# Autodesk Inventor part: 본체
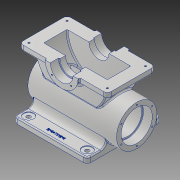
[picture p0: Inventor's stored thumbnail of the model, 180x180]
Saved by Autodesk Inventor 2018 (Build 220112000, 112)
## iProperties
Created: 2023-07
Part Number: 본체
Material: 알루미늄 6061
Document SubType Name: Modeling
Designer: 강의실04
Density: 2.7 g/cm^3
Appearance: 알루미늄 - 평지
Mass: 5728.17 g
Surface Area: 2845.94 cm^2
Volume: 2121.54 cm^3
Author: 강의실04
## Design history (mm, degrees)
sketch "스케치1"
  geometry: C1 r 55 at (0, 0); 1 further point
  constraints: 1 centre point, 1 coincident
  dimensions: "d0" = 110 diameter of C1
extrude "돌출1" new body sketch "스케치1" distance "d1" = 107; taper "d3" = 0 deg; dims "d2" = 135, "d4" = 0
node "작업 평면5"
sketch "스케치31"
  geometry: L1 (65, 120)-(-65, 120); L2 (-65, 120)-(-65, -120); L3 (-65, -120)-(65, -120); L4 (65, -120)-(65, 120); L5 (65, 120)-(-65, -120); L6 (-65, 120)-(65, -120); 1 further point
  constraints: 12 end point, 2 midpoint, 2 parallel, 1 horizontal, 1 perpendicular
  dimensions: "d120" = 130 distance of L3.end L2.end; "d121" = 240 distance of L2.end L1.end
extrude "돌출14" join sketch "스케치31" distance "d122" = 15; taper "d123" = 0 deg
sketch "스케치33"
  geometry: L1 (100, -120)-(100, 120) reference; L2 (100, 100)-(100, -100); A1 r 100 centre (100, 0) between (100, 100) and (100, -100); 1 further point
  constraints: 2 end point, 2 point on circle, 2 point on line, 1 centre point, 1 midpoint
  dimensions: "d124" = 200 diameter of A1
extrude "돌출15" join sketch "스케치33" stored distance "d125" = 90; taper "d126" = 0 deg
sketch "스케치45"
  geometry: L1 (-70, 100)-(70, 100); L2 (65, 100)-(-65, 100) reference; L3 (-70, 100)-(-70, 85); L4 (-70, 85)-(70, 85); L5 (70, 85)-(70, 100); 2 further points
  constraints: 8 end point, 2 midpoint, 1 horizontal, 1 perpendicular, 1 vertical, 1 vertical alignment
  dimensions: "d153" = 140 distance of L1.start L1.end; "d154" = 15 distance of L1.start L3.end; "d155" = 140 distance of L3.end L4.end
revolve "회전2" sketch "스케치45" stored, may be unused: angle "d156" = 90 deg
sketch "스케치46"
  geometry: L1 (-120, 0)-(-15, 0) reference; L2 (-45, 0)-(45, 0); A1 r 45 centre (0, 0) between (-45, 0) and (45, 0); 2 further points
  constraints: 2 end point, 2 point on circle, 1 centre point, 1 coincident, 1 collinear, 1 horizontal alignment, 1 point on line
  dimensions: "d157" = 90 diameter of A1
extrude "돌출21" join sketch "스케치46" stored distance "d158" = 23; taper "d159" = 0 deg
sketch "스케치49"
  geometry: C1 r 31 at (0, 0); A1 r 45 centre (0, 0) between (-45, 0) and (45, 0) reference; 1 further point
  constraints: 1 centre point, 1 coincident
  dimensions: "d165" = 62 diameter of C1
extrude "돌출22" cut sketch "스케치49" distance "d166" = 23; taper "d167" = 0 deg
sketch "스케치50"
  geometry: C1 r 31 at (0, 0); A1 r 45 centre (0, 0) between (-45, 0) and (45, 0) reference; 1 further point
  constraints: 1 centre point, 1 coincident
  dimensions: "d168" = 62 diameter of C1
extrude "돌출23" cut sketch "스케치50" distance "d169" = 23; taper "d170" = 0 deg
sketch "스케치51"
  geometry: C1 r 27.5 at (0, 0); A1 r 15 centre (0, 0) between (15, 0) and (-15, 0) reference; 1 further point
  constraints: 1 centre point, 1 coincident
  dimensions: "d171" = 55 diameter of C1
extrude "돌출24" cut sketch "스케치51" stored distance "d172" = 23; taper "d173" = 0 deg
fillet "모깎기3" dims "d174" = 10
sketch "스케치52"
  geometry: 3 further points
  constraints: 1 horizontal alignment
  dimensions: "d175" = 52 horizontal distance of point (0, 0) point (52, 107); "d176" = 104 distance of point (-52, 107) point (52, 107); "d177" = 107 vertical distance of point (0, 0) point (52, 107)
hole "구멍2" sketch "스케치52" at (52, 107), (-52, 107) diameter "d178" = 4.917; stored, may be unused: countersink angle "d182" = 90 deg, drill point angle "d184" = 118 deg; dims "d179" = 12, "d180" = 4, "d181" = 2, "d183" = 17.1
node "작업 평면6"
sketch "스케치53"
  geometry: L1 (-100, -100)-(100, -100); L2 (100, -100)-(100, 100); L3 (100, 100)-(-100, 100); L4 (-100, 100)-(-100, -100); L5 (55, 107)-(-55, 107) reference; 1 further point
  constraints: 8 end point, 2 parallel, 1 horizontal, 1 perpendicular
  dimensions: "d189" = 200 distance of L3.end L2.end; "d190" = 200 distance of L2.end L1.end; "d192" = 100 horizontal distance of L3.end point (0, 0); "d199" = 7 distance between parallel lines of L3 L5
extrude "돌출25" join sketch "스케치53" distance "d193" = 15; taper "d194" = 0 deg
fillet "모깎기5" dims "d200" = 10
sketch "스케치55"
  geometry: 3 further points
  constraints: 1 vertical alignment
  dimensions: "d201" = 80 horizontal distance of point (80, -80) point (0, 0); "d202" = 160 distance of point (80, 80) point (80, -80); "d203" = 80 horizontal distance of point (80, -80) point (0, 0)
hole "구멍3" sketch "스케치55" at (80, -80), (80, 80) diameter "d204" = 11; stored, may be unused: countersink angle "d208" = 90 deg, drill point angle "d210" = 118 deg; dims "d205" = 12, "d206" = 28, "d207" = 2, "d209" = 17.1
sketch "스케치57"
  geometry: L1 (100, 45)-(100, 31) reference; C1 r 87 at (100, 0); A1 r 27.5 centre (100, 0) between (100, 27.5) and (100, -27.5) reference; 1 further point
  constraints: 1 centre point, 1 coincident
  dimensions: "d214" = 174 diameter of C1
extrude "돌출26" cut sketch "스케치57" stored distance "d215" = 64; taper "d216" = 0 deg
sketch "스케치58"
  geometry: C1 r 55 at (0, 0) reference; C2 r 42.5 at (0, 0)
  constraints: 1 centre point, 1 coincident
  dimensions: "d217" = 85 diameter of C2
extrude "돌출27" cut sketch "스케치58" distance "d218" = 25; taper "d219" = 0 deg
sketch "스케치59"
  geometry: C1 r 55 at (0, 0) reference; C2 r 42.5 at (0, 0)
  constraints: 1 centre point, 1 coincident
  dimensions: "d220" = 85 diameter of C2
extrude "돌출28" cut sketch "스케치59" distance "d221" = 25; taper "d222" = 0 deg
sketch "스케치60"
  geometry: C1 r 42.5 at (0, 0) reference; C2 r 38.5 at (0, 0)
  constraints: 1 centre point, 1 coincident
  dimensions: "d223" = 77 diameter of C2
extrude "돌출29" cut sketch "스케치60" extent not by distance; stored distance "d224" = 25; taper "d225" = 0 deg
sketch "스케치61" dims "d226" = 97
  geometry: C1 r 42.5 at (0, 0) reference; C2 r 55 at (0, 0) reference; 2 further points
  constraints: 2 vertical alignment, 1 coincident, 2 other
hole "구멍4" sketch "스케치61" at (0, 48.5) diameter "d227" = 4.134; stored, may be unused: countersink angle "d231" = 90 deg, drill point angle "d233" = 118 deg; dims "d228" = 12, "d229" = 28, "d230" = 2, "d232" = 12
sketch "스케치62" dims "d237" = 97
  geometry: C1 r 42.5 at (0, 0) reference; C2 r 55 at (0, 0) reference; 2 further points
  constraints: 2 vertical alignment, 1 coincident, 2 other
hole "구멍5" sketch "스케치62" at (0, 48.5) diameter "d238" = 4.134; stored, may be unused: countersink angle "d242" = 90 deg, drill point angle "d244" = 118 deg; dims "d239" = 10, "d240" = 28, "d241" = 2, "d243" = 12
fillet "모깎기6" dims "d248" = 1.1
sketch "스케치63"
  geometry: L1 (0, 0)-(26.163, -26.163); L2 (0, 0)-(37, 0); L3 (0, 0)-(-26.163, -26.163); L4 (0, 0)-(37, 0); A1 r 45 centre (0, 0) between (-45, 0) and (45, 0) reference; A2 r 37 centre (0, 0) between (26.163, -26.163) and (-26.163, -26.163); 3 further points
  constraints: 8 end point, 3 coincident, 2 equal length, 2 horizontal, 2 point on circle, 1 centre point
  dimensions: "d249" = 74 diameter of A2; "d251" = 45 deg angle of L1 L2; "d252" = 135 deg angle of L3 L4
hole "구멍6" sketch "스케치63" at (26.163, -26.163), (-26.163, -26.163) diameter "d253" = 4.134; stored, may be unused: countersink angle "d257" = 90 deg, drill point angle "d259" = 118 deg; dims "d254" = 10, "d255" = 28, "d256" = 2, "d258" = 12
fillet "모깎기7" dims "d260" = 1
fillet "모깎기10" dims "d263" = 3
fillet "모깎기11" dims "d264" = 3
fillet "모깎기12" dims "d265" = 3
fillet "모깎기13" dims "d266" = 3
fillet "모깎기14" dims "d267" = 3
fillet "모깎기15" dims "d268" = 3
fillet "모깎기16" dims "d269" = 15
fillet "모깎기17" dims "d270" = 3
fillet "모깎기18" dims "d271" = 3
fillet "모깎기19" dims "d272" = 3
fillet "모깎기20" dims "d273" = 3
sketch "스케치65"
  geometry: L1 (63.246, 97)-(90, 97) reference; L2 (63.246, -97)-(63.246, 97) reference; L3 (90, -97)-(63.246, -97) reference; L4 (97, 90)-(97, -90) reference; L5 (100, -90)-(100, 90) reference; C1 r 14 at (80, 80) reference; C2 r 14 at (80, -80) reference; A1 r 7 centre (90, -90) between (90, -97) and (97, -90) reference; A2 r 7 centre (90, 90) between (97, 90) and (90, 97) reference; 2 further points
  constraints: 1 horizontal alignment, 1 other
  dimensions: "d277" = 15 distance from line of L5 point (85, 0)
feature "엠보싱2" sketch "스케치65" dims "d278" = 0.5, "d279" = 0
node "솔리드1"
pattern_linear "직사각형 패턴2" dims "d187" = 214
pattern_linear "직사각형 패턴3" dims "d213" = 160
pattern_circular "원형 패턴1" dims angle "d235" = 360 deg
pattern_circular "원형 패턴2" dims angle "d246" = 360 deg
mirror "미러1"
